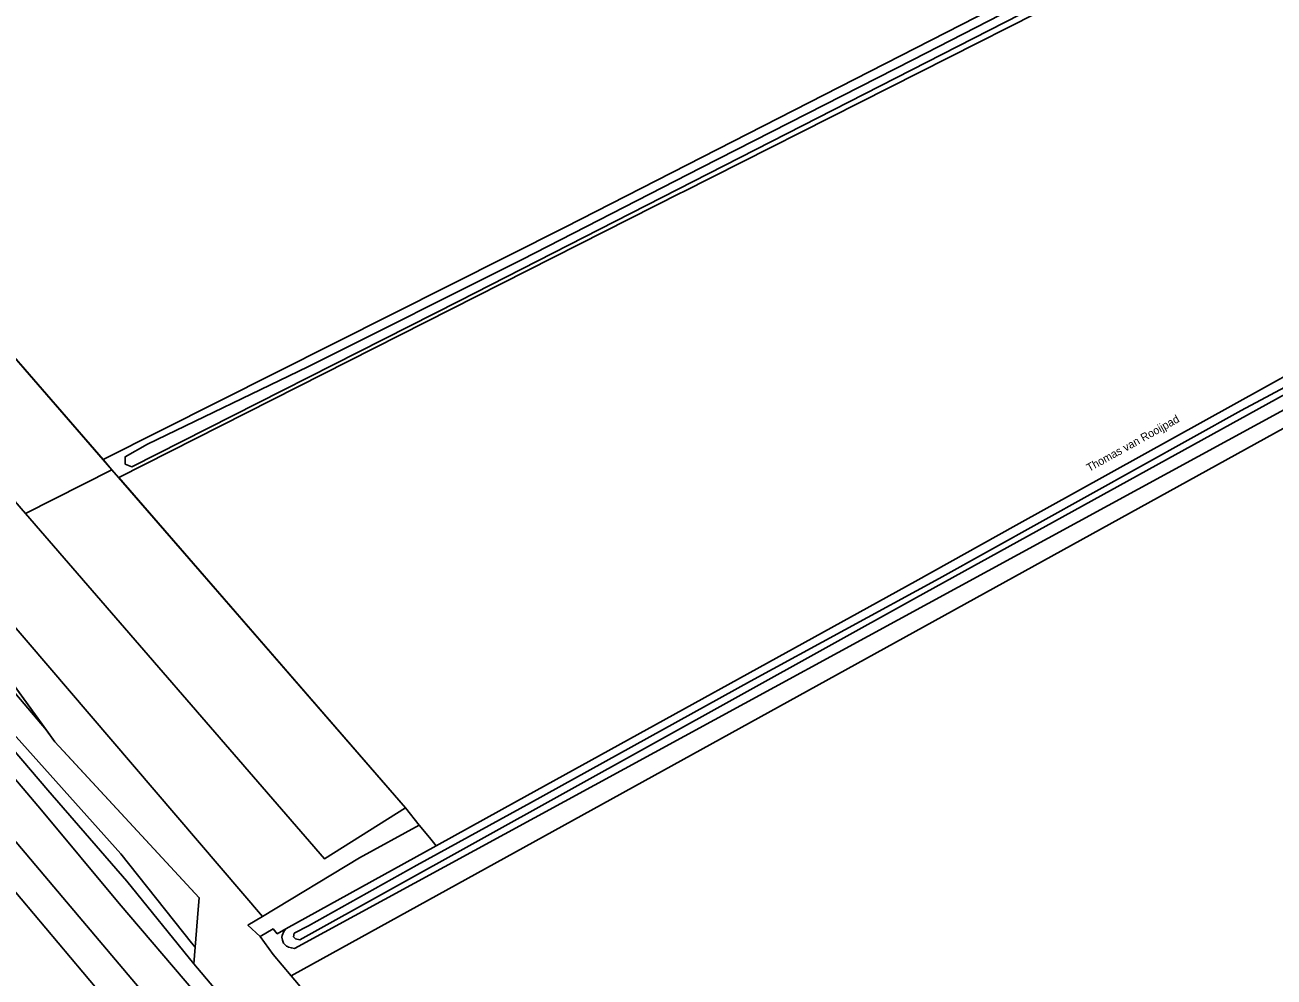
# Model space of a CAD drawing. Extents: x 164494 to 166241, y 382475 to 384494.
# Drawn here: x 165198.1 to 165354.3, y 382608.2 to 382727.2 of the extents above; entities that cross this region are included whole.
import ezdxf

# ---------------------------------------------------------------- set-up
doc = ezdxf.new("R2010")
doc.units = 0
for name, color, linetype in [('IMGEO_Grasland_agrarisch', 7, 'Continuous'), ('IMGEO_Grasland_overig', 7, 'Continuous'), ('IMGEO_Groenvoorziening', 7, 'Continuous'), ('IMGEO_Hek', 7, 'Continuous'), ('IMGEO_Loofbos', 7, 'Continuous'), ('IMGEO_Openbare_ruimte_label', 7, 'Continuous'), ('IMGEO_Spoor', 7, 'Continuous'), ('IMGEO_Spoorbaan_halfverhard', 7, 'Continuous'), ('IMGEO_Struiken', 7, 'Continuous'), ('IMGEO_Waterloop', 7, 'Continuous')]:
    doc.layers.add(name, color=color, linetype=linetype)

msp = doc.modelspace()

# ---------------------------------------------------------------- linework, layer by layer
at = {"layer": 'IMGEO_Grasland_agrarisch'}
for points in [[(165249.54, 382624.64), (165259.71, 382630.25), (165309.39, 382657.69), (165322.04, 382664.7), (165388.32, 382701.46), (165345.24, 382750), (165324.77, 382773.07), (165324.49, 382773.39), (165325.35, 382774.18)], [(165209.86, 382670.66), (165280.13, 382706.24), (165280.34, 382706.35), (165332.05, 382732.53), (165347.1, 382741.03), (165345.65, 382742.9), (165265.64, 382701.97), (165207.89, 382672.93)], [(165262.78, 382578.65), (165257.29, 382578.44), (165248.77, 382587.82), (165231.39, 382608.37)]]:
    msp.add_lwpolyline(points, dxfattribs=at)
at = {"layer": 'IMGEO_Grasland_overig'}
for points in [[(165392.23, 382699.91), (165359.77, 382681.45), (165231.84, 382611.82), (165231.44, 382611.88), (165231.07, 382611.98), (165230.95, 382612.04), (165230.81, 382612.11), (165230.46, 382612.49), (165230.31, 382612.83), (165230.25, 382613.22), (165230.27, 382613.43), (165230.5, 382613.93), (165230.74, 382614.26)], [(165425.5, 382538.24), (165418.91, 382549.58), (165416.19, 382554.47), (165400.96, 382584.41), (165388.9, 382607.3), (165379.91, 382625.45), (165374.99, 382635.66), (165355.79, 382676.99), (165231.39, 382608.37)], [(165252.45, 382569.64), (165239.17, 382583.35), (165230.31, 382593.23), (165219.35, 382606.34), (165209.89, 382617.44), (165200.19, 382629.1), (165186.58, 382645.14)], [(165247.42, 382627.24), (165248.7, 382625.67), (165249.54, 382624.64)], [(165249.54, 382624.64), (165230.74, 382614.26)], [(165227.54, 382613.3), (165226, 382614.71), (165227.82, 382615.8)], [(165230.74, 382614.26), (165229.66, 382613.66), (165229.14, 382614.26), (165227.54, 382613.3)], [(165231.39, 382608.37), (165229.16, 382611.05), (165227.54, 382613.3)], [(165219.26, 382609.88), (165252.19, 382570.91)]]:
    msp.add_lwpolyline(points, dxfattribs=at)
at = {"layer": 'IMGEO_Groenvoorziening'}
msp.add_lwpolyline([(165200.81, 382639.08), (165188.03, 382656.73)], dxfattribs=at)
at = {"layer": 'IMGEO_Hek'}
for points in [[(165012.89, 382863.66), (165025.74, 382848.52), (165028.15, 382845.7), (165085.5, 382780.16), (165088.54, 382776.69), (165137.4, 382721.35), (165139.82, 382718.71), (165140.36, 382718.08), (165158.11, 382697.26), (165174.9, 382674.75), (165177.7, 382671), (165201.86, 382637.62), (165219.91, 382618.16), (165219.79, 382616.68), (165219.42, 382611.97), (165219.26, 382609.88), (165252.19, 382570.91), (165254.3, 382568.42), (165248.76, 382563.58)], [(165198.2, 382666.19), (165154.04, 382717.2), (165164.03, 382723.48), (165209, 382671.65)], [(165231.39, 382608.37), (165355.79, 382676.99), (165374.99, 382635.66), (165379.91, 382625.45), (165388.9, 382607.3), (165400.96, 382584.41)], [(165209, 382671.65), (165245.68, 382629.39), (165235.56, 382623.03)], [(165235.56, 382623.03), (165198.2, 382666.19)]]:
    msp.add_lwpolyline(points, dxfattribs=at)
at = {"layer": 'IMGEO_Loofbos'}
for points in [[(165198.2, 382666.19), (165154.04, 382717.2), (165164.03, 382723.48)], [(165207.89, 382672.93), (165164.03, 382723.48)], [(165158.11, 382697.26), (165227.82, 382615.8)], [(165209, 382671.65), (165198.2, 382666.19)], [(165209, 382671.65), (165207.89, 382672.93)], [(165209.86, 382670.66), (165209, 382671.65)], [(165245.68, 382629.39), (165209.86, 382670.66)], [(165245.68, 382629.39), (165235.56, 382623.03), (165198.2, 382666.19)], [(165247.42, 382627.24), (165245.68, 382629.39)], [(165227.82, 382615.8), (165239.96, 382623.12), (165247.42, 382627.24)]]:
    msp.add_lwpolyline(points, dxfattribs=at)
at = {"layer": 'IMGEO_Spoor'}
msp.add_lwpolyline([(164971.84, 382886.62), (165028.93, 382818.52), (165059.9, 382781.2), (165071.68, 382767.17), (165111.26, 382719.76), (165163.2, 382658.4), (165174.6, 382645.25), (165185.3, 382632.69), (165237.74, 382570.35), (165244.67, 382561.92)], dxfattribs=at)
at = {"layer": 'IMGEO_Spoorbaan_halfverhard'}
msp.add_lwpolyline([(165243.91, 382569.37), (165244.09, 382569.62), (165243.83, 382570.49), (165243.39, 382571.11), (165239.07, 382575.84), (165221.69, 382595.91), (165201.75, 382619.52), (165174.33, 382651.99)], dxfattribs=at)
at = {"layer": 'IMGEO_Struiken'}
for points in [[(165102.09, 382753.62), (165106.35, 382746.62), (165107.94, 382743.47), (165114.06, 382736.05), (165131.92, 382714.87), (165143.23, 382701.96), (165152.9, 382690.69), (165161.86, 382679.57), (165169.92, 382670.73), (165177.49, 382661.69), (165186.13, 382650.91), (165195.62, 382639.86), (165210.13, 382623.63), (165218.96, 382612.53), (165219.42, 382611.97)], [(165219.26, 382609.88), (165210.87, 382620.22), (165200.98, 382631.61), (165185.78, 382649.4), (165175.22, 382662.33), (165154.96, 382685.6), (165144.53, 382698.21), (165136.21, 382708.43), (165115.16, 382732.85), (165106.98, 382742.59), (165103.31, 382749.23), (165102.23, 382752.61), (165102.09, 382753.62)], [(165135.14, 382715.41), (165137.37, 382712.64), (165145.33, 382704.55), (165155.54, 382693.42), (165165.99, 382681.07), (165171.09, 382674.64), (165182.61, 382660.53), (165200.81, 382639.08)], [(165200.81, 382639.08), (165201.86, 382637.62), (165203.99, 382635.33), (165219.91, 382618.16), (165219.79, 382616.68), (165219.42, 382611.97)], [(165219.42, 382611.97), (165219.26, 382609.88)]]:
    msp.add_lwpolyline(points, dxfattribs=at)
at = {"layer": 'IMGEO_Waterloop'}
for points in [[(165260.26, 382697.93), (165282.62, 382709.37), (165309.1, 382722.9), (165345.24, 382741.47), (165345.87, 382741.61), (165346.28, 382741.57), (165346.42, 382741.56), (165346.51, 382741.39), (165346.18, 382740.99), (165342.3, 382738.78), (165326.46, 382730.57), (165252.44, 382692.77), (165211.51, 382671.99), (165210.67, 382672.35), (165210.67, 382673.27), (165213.45, 382674.84), (165233.49, 382684.53), (165260.26, 382697.93)], [(165358.08, 382682.43), (165309.58, 382655.69), (165232.47, 382612.89), (165231.96, 382613), (165231.71, 382613.25), (165231.77, 382613.71), (165233.56, 382614.64), (165247.12, 382622.24), (165261.32, 382630), (165288.82, 382645.23), (165312.39, 382658.04), (165350.14, 382679.06), (165369.12, 382689.16)]]:
    msp.add_lwpolyline(points, dxfattribs=at)

# ---------------------------------------------------------------- texts
at = {"layer": 'IMGEO_Openbare_ruimte_label'}
msp.add_text('Thomas van Rooijpad', height=1, rotation=29.0268, dxfattribs=at).set_placement((165331.16, 382671.37))

doc.saveas('drawing.dxf')
